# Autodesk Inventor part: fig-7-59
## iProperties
Shininess: 64.0
Length Units: 11269
Angle Units: 11279
Time Units: 11290
Mass Units: 11283
Length Display Precision: 3
Angle Display Precision: 2
Compacted: True
Part Number: fig-7-59
Document SubType Name: Modeling
Created: 2003-08
Designer: Owner
Manufacturer: Standard
Standards Organization: Custom
Density: 0.0
Volumn: 0.0
Area: 0.0
PropertySet Name: Model Information
Control State: 0
Master: False
Checked Out: False
Author: Owner
